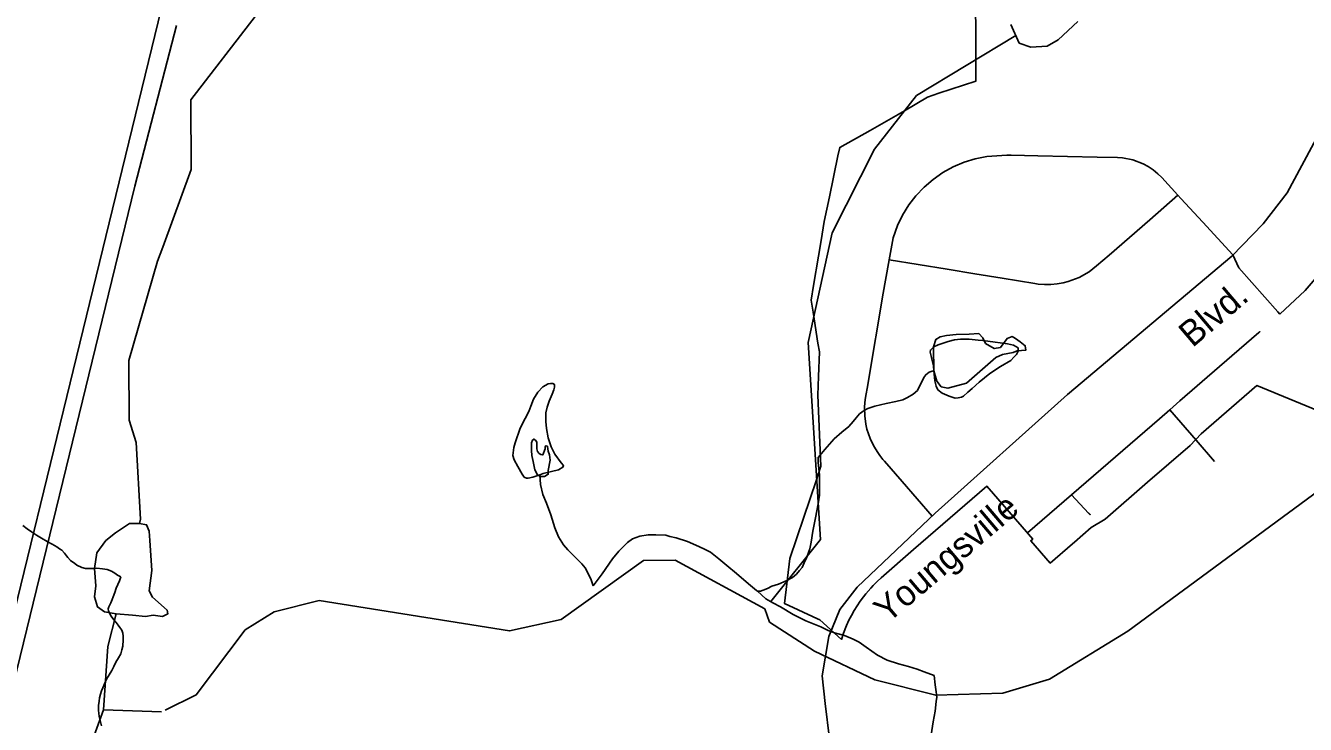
# Model space of a CAD drawing. Extents: x 2126262 to 2293712, y 749403 to 919119.
# Drawn here: x 2147437 to 2152197, y 824349 to 826950 of the extents above; entities that cross this region are included whole.
import ezdxf

# ---------------------------------------------------------------- set-up
doc = ezdxf.new("R2010")
doc.units = 0
for name, color, linetype in [('Exist Boundary Political City Limit New', 7, 'Continuous'), ('Exist Hydrographic Creek Single Shore', 7, 'Continuous'), ('Exist Hydrographic Misc Water Feature', 7, 'Continuous'), ('Exist Hydrographic Pond Under 1500 Sq Ft', 7, 'Continuous'), ('Exist Road Non-System Type 51', 7, 'Continuous'), ('Exist Road Primary US Attributed', 7, 'Continuous'), ('Exist Road Primary US Label', 7, 'Continuous'), ('Exist Utilities Electrical Transmission Line', 7, 'Continuous'), ('Map Preparation Boundary City Limit Buffer Line', 7, 'Continuous')]:
    doc.layers.add(name, color=color, linetype=linetype)

msp = doc.modelspace()

# ---------------------------------------------------------------- linework, layer by layer
at = {"layer": 'Exist Boundary Political City Limit New'}
msp.add_lwpolyline([(2152320.2, 825485.3), (2152015.5, 825610.4), (2151809.2, 825431.3), (2151767.8, 825387.4), (2151609.8, 825250.6), (2151452, 825113.8), (2151399.8, 825081.9), (2151338.2, 825028.4), (2151330.8, 825021.9), (2151247.5, 824949.8), (2151175.2, 825032.8), (2151182.8, 825039.2), (2151143.5, 825084.6), (2151012.2, 825235.6), (2150739.2, 825000), (2150619.2, 824895.2), (2150604, 824881.2), (2150589.2, 824866.6), (2150579.8, 824856.6), (2150561.5, 824835.7), (2150553, 824824.9), (2150540.8, 824808.2), (2150529.2, 824791.1), (2150518.2, 824773.4), (2150508, 824755.4), (2150498.5, 824736.9), (2150490, 824718), (2150478.8, 824688.9), (2150471.2, 824666), (2150390.5, 824738.5), (2150382.5, 824742.2), (2150310.2, 824775.6), (2150259.8, 824799.4), (2150278.5, 824966.6), (2150331.5, 825120.4), (2150376.8, 825256.4), (2150394, 825310.9), (2150383.8, 825574.8), (2150385.8, 825644.9), (2150388.8, 825736.6), (2150383.8, 825769), (2150366, 825883.6), (2150358.5, 825927.9), (2150367.5, 825983.1), (2150385.2, 826091.6), (2150395, 826150.8), (2150406.5, 826221.4), (2150426, 826313.6), (2150458.2, 826465.4), (2150465, 826496.8), (2150578.2, 826560.4), (2150682.5, 826619.1), (2150705.5, 826633), (2150790.5, 826684.4), (2150833, 826698.4), (2150971, 826743.9), (2150968, 827667)], dxfattribs=at)
at = {"layer": 'Exist Hydrographic Creek Single Shore'}
msp.add_line((2147942.4, 824396.3), (2147726.5, 824404), dxfattribs=at)
for points in [[(2147946.7, 826125.7), (2148052.5, 826414.9), (2148051.5, 826674.1), (2148290.4, 826984.1), (2148422.4, 827309.4), (2148529.4, 827477.9), (2148577.4, 827850.9)], [(2147860.4, 825097.4), (2147864.5, 825113), (2147847.4, 825398.8), (2147821.4, 825481.3), (2147820.4, 825704.5), (2147927.4, 826073)], [(2150186.5, 824779.7), (2150203.5, 824730.2), (2150370.4, 824621.7), (2150595.3, 824515.4), (2150821.5, 824458.3), (2151071.5, 824466.2), (2151245.4, 824518.5), (2151536.3, 824696.1), (2152341.4, 825289.8), (2152391.4, 825292)], [(2147955.4, 824402.6), (2148071.4, 824459.2), (2148253.4, 824701.5), (2148361.5, 824768.1), (2148528.4, 824810.6), (2149236.5, 824697.6), (2149428.4, 824739.6), (2149735.4, 824959.7), (2149852.4, 824960.5), (2150186.5, 824779.7)], [(2147726.5, 824404), (2147742.5, 824639.9), (2147773.7, 824761)], [(2146564, 821874.8), (2146681.8, 822212), (2146898, 822500.2), (2146934.5, 822542.8), (2146928.4, 822585.4), (2146934.5, 822628.1), (2146977.1, 822674.7), (2147045.1, 822749.8), (2147116.2, 822867.6), (2147152.7, 822950.8), (2147201.4, 823005.6), (2147221.7, 823064.4), (2147219.7, 823113.1), (2147262.3, 823180.1), (2147317.1, 823216.6), (2147313, 823277.5), (2147388.1, 823350.6), (2147388.1, 823385.1), (2147380, 823433.8), (2147424.7, 823502.8), (2147493.7, 823586), (2147574.8, 823640.8), (2147553.4, 823928.5), (2147726.5, 824404)]]:
    msp.add_lwpolyline(points, dxfattribs=at)
at = {"layer": 'Exist Hydrographic Misc Water Feature'}
for points in [[(2150207.9, 824806.5), (2150393.4, 825038), (2150347.4, 825770.5), (2150436.4, 826178.8), (2150593.5, 826490.5), (2150750.4, 826690.6), (2151120.1, 826913)], [(2147927.4, 826073), (2147946.7, 826125.7)], [(2147946.7, 826125.7), (2147946.7, 826125.7)], [(2147946.7, 826125.7), (2147946.7, 826125.7)], [(2147946.7, 826125.7), (2147946.7, 826125.7)], [(2147946.7, 826125.7), (2147946.7, 826125.7)], [(2147946.7, 826125.7), (2147946.7, 826125.7)], [(2147946.7, 826125.7), (2147946.7, 826125.7)], [(2147946.7, 826125.7), (2147946.7, 826125.7)], [(2150814.7, 825664.9), (2150812.8, 825684.6), (2150806.5, 825714.8), (2150800.5, 825734.8), (2150802.2, 825742.6), (2150814.3, 825754.6), (2150830.3, 825762.7), (2150868.4, 825774.8), (2150891.8, 825781), (2150914.3, 825783.3), (2150946.1, 825783.3), (2150980, 825779.4), (2150996.4, 825777.8), (2151016, 825776), (2151088.2, 825766.3), (2151110.4, 825760.5), (2151120.2, 825756.6), (2151128.2, 825750.5), (2151128.2, 825738.3), (2151122.5, 825726.6), (2151112.6, 825716.3), (2151100.5, 825704.4), (2151062.8, 825682.1), (2151022.8, 825656.1), (2150983, 825623.6), (2150956.8, 825599.6), (2150941.4, 825585.7), (2150925.4, 825571.5), (2150917, 825567.4), (2150905.3, 825565.2), (2150893.4, 825563.3), (2150871.3, 825571.1), (2150845.2, 825582.7), (2150829.4, 825594.9), (2150823.3, 825608.8), (2150818.8, 825628.5), (2150814.7, 825664.9)], [(2150384.9, 825342.4), (2150408.7, 825372.5), (2150444.1, 825412.6), (2150472, 825436.8), (2150498.3, 825458.8), (2150514.1, 825477.1), (2150525.8, 825491.1), (2150537.9, 825505.1), (2150556.1, 825517.4), (2150569.6, 825525.5), (2150595.7, 825533.7), (2150637.3, 825543.6), (2150673.6, 825551.9), (2150699.6, 825558.1), (2150717.1, 825566.4), (2150737.4, 825578.4), (2150753.4, 825592.6), (2150761.2, 825608.5), (2150771, 825626.5), (2150777.2, 825640.5), (2150784.7, 825650.8), (2150797, 825660.7), (2150808.7, 825664.6), (2150814.7, 825664.9)], [(2149349.4, 825278.5), (2149361.1, 825282.8), (2149419.1, 825297.1), (2149435.3, 825306.8), (2149437.1, 825313), (2149428.9, 825323.2), (2149404.9, 825354.8), (2149391, 825382.9), (2149380.3, 825416.6), (2149374.6, 825450.7), (2149372.1, 825476.6), (2149371.9, 825508.7), (2149376, 825530.8), (2149384, 825552.7), (2149395.5, 825578.6), (2149401.7, 825594.7), (2149403.7, 825604.5), (2149403.7, 825614.7), (2149397.6, 825618.8), (2149389.4, 825618.8), (2149379.7, 825616.7), (2149359.8, 825606.3), (2149341.6, 825586.3), (2149325.8, 825560.3), (2149316, 825534.2), (2149308, 825514.4), (2149294.2, 825488), (2149276.4, 825452.2), (2149257.1, 825397.9), (2149252.8, 825379.8), (2149250.7, 825370.1), (2149249.1, 825350), (2149253.2, 825334), (2149267.6, 825309.9), (2149283.3, 825280.3), (2149291.3, 825270.1), (2149299.8, 825266), (2149305.7, 825266.4), (2149323.3, 825270.2), (2149349.4, 825278.5)], [(2150384.9, 825342.4), (2150384.9, 825324.2), (2150389.2, 825278.5), (2150389.6, 825242.4), (2150389.8, 825202.6), (2150384.1, 825170.5), (2150374, 825118.5), (2150364.4, 825068.4), (2150358.6, 825028.3), (2150352.9, 825002.4), (2150342.9, 824972.3), (2150332.8, 824950.3), (2150325, 824934), (2150315, 824922.2), (2150303.3, 824908.1), (2150289.3, 824896), (2150265.3, 824883.8), (2150237.3, 824871.8), (2150211.8, 824863.5), (2150195.4, 824855.4), (2150179.6, 824849.3), (2150169.6, 824845.2), (2150159.3, 824845.1)], [(2149349.4, 825278.5), (2149351.4, 825242.4), (2149360, 825204.6), (2149373.8, 825172.9), (2149390.4, 825129), (2149404.5, 825081), (2149418.7, 825047.2), (2149436.7, 825017.3), (2149453.3, 824999), (2149469.3, 824983.2), (2149489, 824963.5), (2149505, 824947.3), (2149517.3, 824931.7), (2149529.2, 824911.6), (2149539.7, 824887.7), (2149547.9, 824865.8)], [(2147426.4, 825089.4), (2147442.8, 825077.6), (2147458.2, 825066), (2147476.6, 825053.8), (2147496.3, 825042.3), (2147516.4, 825030.3), (2147534.9, 825020.7), (2147553.1, 825010.6), (2147563, 825003.1), (2147571, 824997.4), (2147581, 824986.9), (2147589.2, 824977.2), (2147593.3, 824971.3), (2147603.4, 824959.6), (2147619.1, 824947.9), (2147627.6, 824941.8), (2147645.6, 824933.3), (2147659.5, 824929.6), (2147671.8, 824929.3), (2147689.7, 824929.9), (2147701.8, 824930.5), (2147722.3, 824929), (2147739.9, 824925.6), (2147755.7, 824920.3), (2147768, 824912.8), (2147777.9, 824905.2), (2147791.2, 824898.3)], [(2150159.3, 824845.1), (2150155.4, 824847.3), (2150125.3, 824873), (2150081, 824910.9), (2150045.3, 824940.6), (2150015.2, 824966.3), (2149984.6, 824990.4), (2149964.5, 824999.9), (2149940.7, 825012), (2149898.7, 825029.8), (2149856.3, 825043.5), (2149832.5, 825049.1), (2149818.3, 825053.3), (2149780.4, 825054.9), (2149752.3, 825054.7), (2149720.7, 825050.6), (2149694.3, 825040.4), (2149675, 825026.3), (2149642.8, 824994.2), (2149619, 824966.2), (2149581.1, 824909.9), (2149547.9, 824865.8)], [(2147791.2, 824898.3), (2147786.3, 824884.4), (2147774, 824856.7), (2147768.2, 824840.5), (2147762.3, 824824.4), (2147758.4, 824814.4), (2147753, 824802.3), (2147746.1, 824786.6), (2147744.2, 824779.7), (2147745, 824772.2), (2147747.1, 824766.2), (2147755.3, 824752), (2147764.9, 824738.8), (2147773.6, 824729), (2147781.1, 824718.9), (2147787.5, 824710.6), (2147794.7, 824699.8), (2147798, 824689.2), (2147799, 824677.6), (2147799.8, 824664.9), (2147798, 824640.5), (2147795.1, 824626.7), (2147790.4, 824612.8), (2147781.8, 824597.5), (2147772.5, 824580.6), (2147764.9, 824565.1), (2147756.9, 824550.5), (2147747.1, 824534.2), (2147737.1, 824518.2), (2147729.5, 824500.3), (2147724.1, 824486.1), (2147718.8, 824473.9), (2147715.1, 824461.9), (2147711.8, 824448.2), (2147709.8, 824435.9), (2147708.1, 824420.4), (2147708.1, 824402.1), (2147709.2, 824390.6), (2147710.2, 824379.9), (2147712.7, 824368.6), (2147716.8, 824354.5), (2147718.4, 824344.5)], [(2150815.5, 824531.2), (2150779, 824544.8), (2150753.2, 824554.8), (2150720.8, 824564.6), (2150682.8, 824574.4), (2150641, 824588), (2150604.7, 824607.7), (2150562.9, 824637.6), (2150536.6, 824655.3), (2150514.3, 824667.2), (2150482.7, 824680.9), (2150444.8, 824690.7), (2150422.2, 824698.6), (2150394.3, 824712.6), (2150338.5, 824734.4), (2150292, 824758.1), (2150244.2, 824787.6), (2150215.9, 824801.7), (2150190.1, 824817.3), (2150159.3, 824845.1)], [(2150804.8, 824310.9), (2150812.4, 824359.2), (2150819.8, 824399.1), (2150823.7, 824435), (2150825.5, 824451), (2150823.3, 824471.2), (2150819.6, 824496.9), (2150815.5, 824531.2)]]:
    msp.add_lwpolyline(points, dxfattribs=at)
at = {"layer": 'Exist Hydrographic Pond Under 1500 Sq Ft'}
for points in [[(2151101.1, 826954.9), (2151132.6, 826885.3), (2151175.2, 826869.6), (2151235.8, 826874.1), (2151277.7, 826897.7), (2151350.3, 826966.2)], [(2150814.7, 825664.9), (2150826.3, 825626.7), (2150842.3, 825606), (2150866.8, 825601.3), (2150935.8, 825619.1), (2151044.9, 825715.3), (2151070.5, 825725.8), (2151110.1, 825733.3), (2151125.2, 825739.9), (2151157.2, 825742.8), (2151154.4, 825758.8), (2151135.5, 825773.9), (2151118.6, 825785.2), (2151105.4, 825792.8), (2151087.4, 825785.2), (2151062, 825752.2), (2151039.4, 825748.4), (2151007.2, 825767.2), (2150996.9, 825788), (2150981.9, 825805), (2150946, 825802.2), (2150898, 825800.3), (2150862.1, 825796.5), (2150838.6, 825791.8), (2150822.5, 825782.4), (2150813.8, 825754.3), (2150814.7, 825664.9)], [(2149369.2, 825375.2), (2149360.3, 825352.7), (2149353.3, 825354), (2149346.8, 825357.2), (2149340.7, 825365.3), (2149337.8, 825375.2), (2149337.8, 825399.9), (2149332.7, 825407.4), (2149326.6, 825411.2), (2149321.4, 825406.9), (2149317.6, 825397.7), (2149317.6, 825368.5), (2149319.8, 825350.5), (2149324.3, 825328), (2149331.1, 825296.6), (2149340, 825278.6), (2149353.5, 825271.8), (2149367, 825271.8), (2149380.5, 825280.8), (2149380.6, 825288.7), (2149379.6, 825294.7), (2149387.2, 825332.5), (2149385, 825352.7), (2149380.5, 825366.2), (2149378.2, 825384.2), (2149376.1, 825385.6), (2149372.9, 825386.1), (2149370.6, 825385.4), (2149369.2, 825382), (2149369.2, 825375.2)], [(2147860.4, 825097.4), (2147822.8, 825097.6), (2147770.7, 825062), (2147735.1, 825033.6), (2147702, 824988.5), (2147692.6, 824930.1), (2147697.2, 824865.2), (2147692.5, 824824.9), (2147704.3, 824786.9), (2147730.4, 824768), (2147773.7, 824761), (2147834.7, 824756.1), (2147882.1, 824751.4), (2147910.5, 824756.1), (2147946.1, 824751.4), (2147965, 824760.9), (2147962.7, 824775.1), (2147908.2, 824822.5), (2147896.3, 824846.2), (2147905.8, 824922.1), (2147898.7, 825033.6), (2147896.3, 825069.1), (2147886.8, 825092.9), (2147860.4, 825097.4)]]:
    msp.add_lwpolyline(points, dxfattribs=at)
at = {"layer": 'Exist Road Non-System Type 51'}
msp.add_line((2151326.5, 825203.7), (2151163.1, 825062), dxfattribs=at)
for points in [[(2152547, 826519.1), (2152393, 826222.7), (2152284.5, 826068.7), (2152195.7, 825964.3), (2152101.6, 825876.2)], [(2151722.2, 826319.5), (2151662.2, 826384.8), (2151647.8, 826399.1), (2151630.6, 826413.3), (2151611.9, 826425.8), (2151593.3, 826435.9), (2151555.3, 826450.3), (2151517, 826457.7), (2151498.3, 826458.9), (2151422, 826460.6), (2151311.9, 826463.1), (2151202, 826465.6), (2151102, 826467.9), (2151085.6, 826468.3), (2151012.3, 826463.6), (2150968.3, 826454.7), (2150927.3, 826441.9), (2150886, 826424.2), (2150848.3, 826403.4), (2150811.6, 826377.7), (2150779, 826349.6), (2150748.2, 826317), (2150722, 826282.9), (2150698.4, 826244.7), (2150679.8, 826206), (2150663.6, 826160.5), (2150648.8, 826078.9)], [(2151722.2, 826319.5), (2151617.5, 826227.9), (2151542, 826162.1), (2151466.7, 826096.3), (2151420.2, 826055.7), (2151392.7, 826034.5), (2151355, 826013), (2151313.8, 825997.5), (2151296.3, 825993), (2151273.2, 825989), (2151250, 825986.8), (2151226.4, 825986.7), (2151202.4, 825988.5), (2151190.7, 825990.1), (2151068.7, 826010.1), (2150967.2, 826026.7), (2150864.5, 826043.6), (2150648.8, 826078.9)], [(2151927.1, 826097.2), (2151815.3, 826218.6), (2151733.5, 826307.3), (2151722.2, 826319.5)], [(2150648.8, 826078.9), (2150624, 825941.1), (2150608, 825842.9), (2150589.5, 825734.1), (2150569.2, 825613.8), (2150561, 825566), (2150558.6, 825547.2), (2150557.3, 825528.8), (2150558, 825497.8), (2150562.1, 825466.9), (2150565.9, 825448.8), (2150571.3, 825431.1), (2150577.8, 825413.7), (2150585, 825397.2), (2150593.8, 825380.9), (2150603.3, 825365.1), (2150613.9, 825350), (2150625.4, 825335.9), (2150631.2, 825329.2), (2150696.8, 825253.5), (2150807.9, 825124.9)], [(2152101.6, 825876.2), (2152101, 825876.7), (2152093.8, 825884.9), (2151948.8, 826048.4), (2151927.1, 826097.2)], [(2152027.8, 825811.6), (2152027.6, 825811.2), (2152026.9, 825810.9), (2152026.7, 825810.6), (2152026.3, 825810.3), (2152025.9, 825809.9), (2152025.5, 825809.6), (2152025.3, 825809.3), (2152024.7, 825808.9), (2152024.5, 825808.6), (2152023.7, 825808.2), (2151877.7, 825681.5), (2151730, 825553.2), (2151692.3, 825520.4)], [(2151692.3, 825520.4), (2151653.5, 825486.9), (2151326.5, 825203.7)], [(2151692.3, 825520.4), (2151790.5, 825407.1), (2151858.8, 825328.5)], [(2151396.4, 825129.7), (2151396.2, 825130), (2151395.8, 825130.4), (2151395.6, 825130.8), (2151395.2, 825131.1), (2151394.8, 825131.4), (2151394.6, 825131.8), (2151394.2, 825132.2), (2151393.7, 825132.6), (2151393.5, 825132.9), (2151393.3, 825133.3), (2151392.7, 825133.6), (2151392.5, 825134), (2151392.3, 825134.4), (2151391.7, 825134.7), (2151391.5, 825135.1), (2151391.1, 825135.4), (2151390.7, 825135.8), (2151390.5, 825136.1), (2151326.5, 825203.7)]]:
    msp.add_lwpolyline(points, dxfattribs=at)
at = {"layer": 'Exist Road Primary US Attributed'}
msp.add_lwpolyline([(2150442.1, 824164.4), (2150410.1, 824426.9), (2150399.6, 824530.9), (2150424.7, 824676.1), (2150465.2, 824776.7), (2150529.3, 824860.5), (2150820.2, 825136.2), (2151312, 825576.8), (2151922.7, 826092.5), (2152039.9, 826212.6), (2152129.2, 826328.5), (2152247, 826547), (2152378.2, 826801.1), (2152546.3, 827136.9), (2152662.1, 827347.8), (2152786.2, 827486), (2152920.2, 827585.1), (2153424.6, 827784.4), (2153584.6, 827880.1), (2153661.3, 827937.4), (2153754.8, 828029.1), (2153807.8, 828091.2), (2153854.5, 828156.1), (2153884.2, 828208.7)], dxfattribs=at)
at = {"layer": 'Exist Utilities Electrical Transmission Line'}
for points in [[(2147942.4, 827014.7), (2147017.7, 823224.1), (2146663.6, 821833.2)], [(2146733.8, 821803.8), (2147842.3, 826353.1), (2147997.5, 826950.4)]]:
    msp.add_lwpolyline(points, dxfattribs=at)
at = {"layer": 'Map Preparation Boundary City Limit Buffer Line'}
msp.add_lwpolyline([(2152320.2, 825485.3), (2152015.5, 825610.4), (2151809.2, 825431.3), (2151767.8, 825387.4), (2151609.8, 825250.6), (2151452, 825113.8), (2151399.8, 825081.9), (2151338.2, 825028.4), (2151330.8, 825021.9), (2151247.5, 824949.8), (2151175.2, 825032.8), (2151182.8, 825039.2), (2151143.5, 825084.6), (2151012.2, 825235.6), (2150739.2, 825000), (2150619.2, 824895.2), (2150604, 824881.2), (2150589.2, 824866.6), (2150579.8, 824856.6), (2150561.5, 824835.7), (2150553, 824824.9), (2150540.8, 824808.2), (2150529.2, 824791.1), (2150518.2, 824773.4), (2150508, 824755.4), (2150498.5, 824736.9), (2150490, 824718), (2150478.8, 824688.9), (2150471.2, 824666), (2150390.5, 824738.5), (2150382.5, 824742.2), (2150310.2, 824775.6), (2150259.8, 824799.4), (2150278.5, 824966.6), (2150331.5, 825120.4), (2150376.8, 825256.4), (2150394, 825310.9), (2150383.8, 825574.8), (2150385.8, 825644.9), (2150388.8, 825736.6), (2150383.8, 825769), (2150366, 825883.6), (2150358.5, 825927.9), (2150367.5, 825983.1), (2150385.2, 826091.6), (2150395, 826150.8), (2150406.5, 826221.4), (2150426, 826313.6), (2150458.2, 826465.4), (2150465, 826496.8), (2150578.2, 826560.4), (2150682.5, 826619.1), (2150705.5, 826633), (2150790.5, 826684.4), (2150833, 826698.4), (2150971, 826743.9), (2150968, 827667)], dxfattribs=at)

# ---------------------------------------------------------------- texts
at = {"layer": 'Exist Road Primary US Label'}
for s, p in [('Blvd.', (2151776.6, 825749.6)), ('Youngsville', (2150642.7, 824723.2))]:
    msp.add_text(s, height=95, rotation=40.2672, dxfattribs=at).set_placement(p)

doc.saveas('drawing.dxf')
